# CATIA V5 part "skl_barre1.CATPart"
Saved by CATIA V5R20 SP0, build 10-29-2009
Part number: skl_barre1
Publications: "Barre_1", "Axe_Pivot_G", "Axe_Pivot_b1b9"
Bounding box of the stored display mesh (mm): x 0 to 394.671, y 0 to 313.648, z 0 to 20
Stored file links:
  C:\Users\Matthieu\Desktop\IFMA\Cours 2A\Thinkmotion\skl_barre1.CATPart
  C:\Users\Matthieu\Desktop\IFMA\Cours 2A\Thinkmotion\skl_IAO_bis.CATProduct
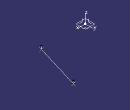
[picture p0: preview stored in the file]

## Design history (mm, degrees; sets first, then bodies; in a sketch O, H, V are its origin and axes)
AxisSystem1: origin (0, 0, 0), X (1, 0, 0), Y (0, 1, 0), Z (0, 0, 1)
Set1
  Point1 "Point.H": linked copy from another document
  Point2 "Point.G": linked copy from another document
  Plane1 "Plan_Ref": linked copy from another document
Body1 (main body)
  Line1 "Barre_1": type PtPt, FirstPoint Point1, SecondPoint Point2
  Line2 "Axe_Pivot_G": type Normal, RefPoint Point2, RefSkin Plane1, Start 0, End 20
  Line3 "Axe_Pivot_b1b9": type Normal, RefPoint Point1, RefSkin Plane1, Start 0, End 20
